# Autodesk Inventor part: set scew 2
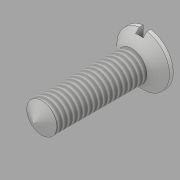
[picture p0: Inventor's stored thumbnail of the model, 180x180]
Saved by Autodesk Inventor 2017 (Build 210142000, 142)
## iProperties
Created: 2016-06
Part Number: set scew 2
Material: Generic
Document SubType Name: Modeling
Designer: CADCIM
Density: 1 g/cm^3
Appearance: Default
Author: CADCIM
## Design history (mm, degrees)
sketch "Sketch1"
  geometry: C1 r 3 at (0, 0); 1 further point
  constraints: 1 centre point, 1 coincident
  dimensions: "d0" = 6 diameter of C1
extrude "Extrusion1" new body sketch "Sketch1" distance "d1" = 18; taper "d2" = 0 deg
sketch "Sketch2"
  geometry: L1 (18, -3)-(18, 3) reference; L2 (18, 0)-(18, -3); L3 (18, -3)-(21, -6); L4 (21, -6)-(21, 0); L5 (21, 0)-(18, 0); 1 further point
  constraints: 8 end point, 2 vertical, 1 midpoint, 1 perpendicular
  dimensions: "d4" = 3 distance of L2.start L2.end; "d5" = 6 distance of L4.end L3.end; "d6" = 3 distance from line of L1.start L4
revolve "Revolution1" sketch "Sketch2" stored, may be unused: angle "d7" = 90 deg
sketch "Sketch3"
  geometry: C1 r 5.25 at (0, 0); 1 further point
  constraints: 1 centre point, 1 coincident
  dimensions: "d8" = 10.5 diameter of C1
extrude "Extrusion2" sketch "Sketch3" distance "d9" = 26.75; taper "d10" = 0 deg
sketch "Sketch4"
  geometry: L1 (-0.75, 8.347)-(0.75, 8.347); L2 (0.75, 8.347)-(0.75, -8.125); L3 (0.75, -8.125)-(-0.75, -8.125); L4 (-0.75, -8.125)-(-0.75, 8.347); L5 (0, 0)-(0, 6.165)
  constraints: 10 end point, 3 parallel, 1 horizontal, 1 perpendicular, 1 other
  dimensions: "d11" = 1.5 distance of L1.start L1.end
extrude "Extrusion3" cut sketch "Sketch4" distance "d12" = 1.5; taper "d13" = 0 deg
sketch "Sketch5"
  geometry: L1 (0, 0)-(0, 3); L2 (0, 3)-(-1.732, 0); L3 (-1.732, 0)-(0, 0); L4 (0, 3)-(0, -3) reference; 1 further point
  constraints: 6 end point, 2 midpoint, 1 perpendicular, 1 point on line, 1 vertical
  dimensions: "d21" = 60 deg angle of L2 L3; "d22" = 3 distance of L1.start L1.end
thread "Thread2" dims "d19" = 10, "d20" = 0
revolve "Revolution3" stored, may be unused: angle "d23" = 90 deg
body "Solid1"
